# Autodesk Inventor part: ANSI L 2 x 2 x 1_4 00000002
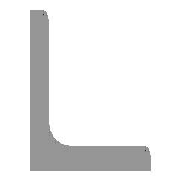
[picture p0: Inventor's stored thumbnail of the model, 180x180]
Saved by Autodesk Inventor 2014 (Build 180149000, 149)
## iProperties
_FrameMemberDoc: Frame Member File
_Version: 15.0.0
_CCFamilyMember: 11
_CCFamilyDisplayName: ANSI L (Equal angles) - Angle Steel
Created: 2007-02
Part Number: ANSI L 2 x 2 x 1_4 00000002
Material: Steel, Mild
Document SubType Name: Modeling
Standard: AISC
Designer: Autodesk, Inc.
Size Designation: L 2 x 2 x 1/4
Stock Number: L 2 x 2 x 1/4
Density: 7.86 g/cm^3
Description: Angle Steel
Standards Organization: ANSI
Language: en-US
Categories: <MemberInstance><Categories><Category DisplayName="Structural Shapes" InternalName="089c4875-fa83-4c05-b084-43b9cc11f5ed" Mnemonic="GRDR"><CategoryParameter Dis
Mass: 4946.82 g
Surface Area: 2058.23 cm^2
Volume: 629.366 cm^3
Appearance: Steel
IsCustomPart: 1
G_L: 42.000 in
G_W: 2.000 in
G_H: 2.000 in
+4F5F36E9-8B8F-4344-9F4B-B9E790CCB65B+CUTDETAIL1: Miter 45.00 deg
+A0A31E8A-0585-471B-91FB-4B501FC77DC9+CUTDETAIL2: Miter 45.00 deg
Author: Autodesk, Inc.
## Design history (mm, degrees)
node "Start plane"
node "End plane"
sketch "Sketch"
  geometry: L1 (50.8, 0)-(0, 0); L2 (0, 0)-(0, 50.8); L3 (0, 50.8)-(3.302, 50.8); L4 (6.35, 47.752)-(6.35, 12.7); L5 (12.7, 6.35)-(47.752, 6.35); L6 (50.8, 3.302)-(50.8, 0); L7 (0, -11.041)-(0, 31.538); L8 (-11.041, 0)-(31.538, 0); L9 (0, 63.926)-(0, -23.536) reference; L10 (-23.536, 0)-(63.926, 0) reference; A1 r 6.35 centre (12.7, 12.7) between (6.35, 12.7) and (12.7, 6.35); A2 r 3.048 centre (3.302, 47.752) between (6.35, 47.752) and (3.302, 50.8); A3 r 3.048 centre (47.752, 3.302) between (50.8, 3.302) and (47.752, 6.35); 3 further points
  constraints: 16 end point, 6 point on circle, 6 point on line, 6 tangent, 4 parallel, 3 centre point, 2 collinear, 1 equal radius, 1 horizontal, 1 perpendicular
  dimensions: "d0" = 50.8 distance between parallel lines of L6 L2 (= G_H); "d1" = 50.8 distance between parallel lines of L3 L1 (= G_H); "d2" = 6.35 distance between parallel lines of L2 L4 (= G_T); "d3" = 6.35 distance between parallel lines of L1 L5 (= G_T); "d10" = 0 distance between parallel lines of L7 L2 (computed from ex); "d11" = 0 distance between parallel lines of L8 L1 (computed from d10); "d14" = 6.35 radius of A1 (= G_IR); "d15" = 3.048 radius of A2 (= G_ER)
extrude "Body" new body sketch "Sketch" stored distance "d4" = 1066.8 (= G_L); taper "d5" = 0 deg
node "Driven Length"
  sketch "Sketch4"
    geometry: L1 (0, 0)-(10, 0) reference
    constraints: 2 end point, 1 horizontal
  workplane "Work Plane5"
  sketch "Sketch5"
    geometry: L1 (-2, -6.35)-(12, -6.35) reference; L2 (-2, 1060.45)-(12, 1060.45) reference
    dimensions: "d20" = 1066.8 distance between parallel lines of L1 L2 (derived)
workplane "Work Plane3"
split "Split1"
workplane "Work Plane4"
split "Split2"
sketch "Sketch3"
  geometry: C1 r 25.4 at (723.9, 57.15) reference; C2 r 31.75 at (723.9, 57.15)
  constraints: 1 centre point, 1 coincident
  dimensions: "d16" = 6.35 radial gap between concentric circles of C1 C2
extrude "Extrusion2" cut sketch "Sketch3" distance "d17" = 25.4; taper "d18" = 0 deg
body "Solid1"
node "Reference1"
other parameters: "G_H" = 50.8 [user parameter; used in 2 equation terms], "G_T" = 6.35 [user parameter; used in 2 equation terms], "G_ER" = 3.048 [user parameter; used in 1 equation term], "G_IR" = 6.35 [user parameter; used in 1 equation term], "G_L" = 1066.8 (= d20) [user parameter; used in 1 equation term], "ex" = 0 [user parameter; used in 1 equation term], "G_OFFSET_START" = 6.35 [user parameter; used in 1 equation term], "G_OFFSET_END" = 6.35 [user parameter; used in 1 equation term], "d12" = -6.35 (= -G_OFFSET_START), "d13" = 1060.45 (= G_OFFSET_END + B_L), "B_L" = 1054.1 [user parameter; used in 1 equation term], "d19" = 90 deg
